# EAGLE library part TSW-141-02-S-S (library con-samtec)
THROUGH-HOLE .025" SQ POST HEADER Source: Samtec TSW.pdf
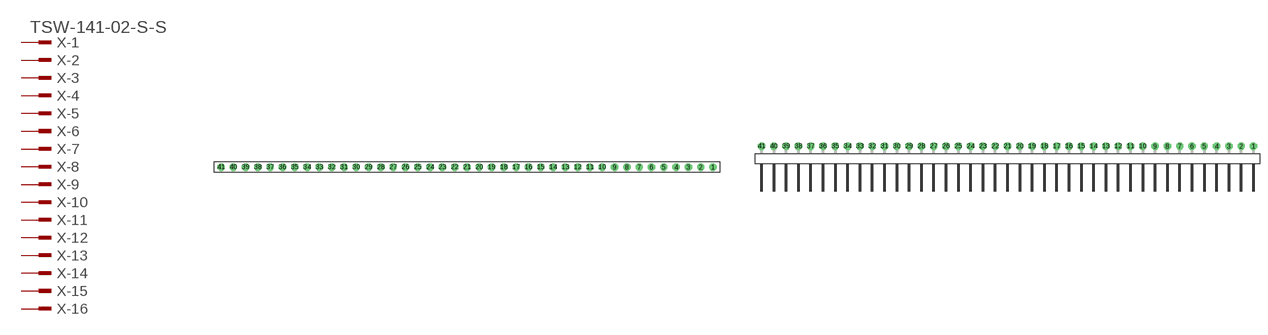
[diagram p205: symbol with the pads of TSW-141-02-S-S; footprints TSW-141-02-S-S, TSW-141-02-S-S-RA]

Designator prefix X; gates -1=MPINV -2=MPIN -3=MPIN -4=MPIN -5=MPIN -6=MPIN -7=MPIN -8=MPIN -9=MPIN -10=MPIN -11=MPIN -12=MPIN -13=MPIN -14=MPIN -15=MPIN -16=MPIN -17=MPIN -18=MPIN -19=MPIN -20=MPIN -21=MPIN -22=MPIN -23=MPIN -24=MPIN -25=MPIN -26=MPIN -27=MPIN -28=MPIN -29=MPIN -30=MPIN -31=MPIN -32=MPIN -33=MPIN -34=MPIN -35=MPIN -36=MPIN -37=MPIN -38=MPIN -39=MPIN -40=MPIN -41=MPIN

## TSW-141-02-S-S (OC_FARNELL: unknown; OC_NEWARK: unknown)  [TSW-141-02-S-S]
1  -1:1  pas
2  -2:1  pas
3  -3:1  pas
4  -4:1  pas
5  -5:1  pas
6  -6:1  pas
7  -7:1  pas
8  -8:1  pas
9  -9:1  pas
10  -10:1  pas
11  -11:1  pas
12  -12:1  pas
13  -13:1  pas
14  -14:1  pas
15  -15:1  pas
16  -16:1  pas
17  -17:1  pas
18  -18:1  pas
19  -19:1  pas
20  -20:1  pas
21  -21:1  pas
22  -22:1  pas
23  -23:1  pas
24  -24:1  pas
25  -25:1  pas
26  -26:1  pas
27  -27:1  pas
28  -28:1  pas
29  -29:1  pas
30  -30:1  pas
31  -31:1  pas
32  -32:1  pas
33  -33:1  pas
34  -34:1  pas
35  -35:1  pas
36  -36:1  pas
37  -37:1  pas
38  -38:1  pas
39  -39:1  pas
40  -40:1  pas
41  -41:1  pas

## TSW-141-02-S-S-RA (OC_FARNELL: unknown; OC_NEWARK: unknown)  [TSW-141-02-S-S-RA]
Pads as for TSW-141-02-S-S

## Footprint TSW-141-02-S-S (pad centres in mm)
THROUGH-HOLE .025" SQ POST HEADER Source: Samtec TSW.pdf
drill 1 pad 1.5 octagon: 1 50.8,0; 2 48.26,0; 3 45.72,0; 4 43.18,0; 5 40.64,0; 6 38.1,0; 7 35.56,0; 8 33.02,0; 9 30.48,0; 10 27.94,0; 11 25.4,0; 12 22.86,0; 13 20.32,0; 14 17.78,0; 15 15.24,0; 16 12.7,0; 17 10.16,0; 18 7.62,0; 19 5.08,0; 20 2.54,0; 21 0,0; 22 -2.54,0; 23 -5.08,0; 24 -7.62,0; 25 -10.16,0; 26 -12.7,0; 27 -15.24,0; 28 -17.78,0; 29 -20.32,0; 30 -22.86,0; 31 -25.4,0; 32 -27.94,0; 33 -30.48,0; 34 -33.02,0; 35 -35.56,0; 36 -38.1,0; 37 -40.64,0; 38 -43.18,0; 39 -45.72,0; 40 -48.26,0; 41 -50.8,0

## Footprint TSW-141-02-S-S-RA (pad centres in mm)
THROUGH-HOLE .025" SQ POST HEADER Source: Samtec TSW.pdf
drill 1 pad 1.5 octagon: 1 50.8,1.524; 2 48.26,1.524; 3 45.72,1.524; 4 43.18,1.524; 5 40.64,1.524; 6 38.1,1.524; 7 35.56,1.524; 8 33.02,1.524; 9 30.48,1.524; 10 27.94,1.524; 11 25.4,1.524; 12 22.86,1.524; 13 20.32,1.524; 14 17.78,1.524; 15 15.24,1.524; 16 12.7,1.524; 17 10.16,1.524; 18 7.62,1.524; 19 5.08,1.524; 20 2.54,1.524; 21 0,1.524; 22 -2.54,1.524; 23 -5.08,1.524; 24 -7.62,1.524; 25 -10.16,1.524; 26 -12.7,1.524; 27 -15.24,1.524; 28 -17.78,1.524; 29 -20.32,1.524; 30 -22.86,1.524; 31 -25.4,1.524; 32 -27.94,1.524; 33 -30.48,1.524; 34 -33.02,1.524; 35 -35.56,1.524; 36 -38.1,1.524; 37 -40.64,1.524; 38 -43.18,1.524; 39 -45.72,1.524; 40 -48.26,1.524; 41 -50.8,1.524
